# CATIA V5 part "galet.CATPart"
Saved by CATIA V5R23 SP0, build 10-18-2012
Part number: galet
Definition: galet
Source: made
Bounding box of the stored display mesh (mm): x -5 to 5, y -15 to 15, z -15 to 15
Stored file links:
  C:\wamp\www\COURS\CONCEPTION GMP1\TITRE 01-CATIA VOLUMIQUE\05--ACTIONNEUR DE VANNE\prof\CORRECTION\Assemblage\galet.CATPart
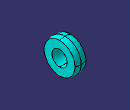
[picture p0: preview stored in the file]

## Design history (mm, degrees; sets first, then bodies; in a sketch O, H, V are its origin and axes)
Body1 "NONE" (main body)
  Solid1 "Manifold Solid #95": solid without history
